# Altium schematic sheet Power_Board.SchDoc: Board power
size A3; Project: STM32MP15-DISCO; Date: Not used; ApprovedBy: Not used; CheckedBy: Not used; Author: Not used; CompanyName: STMicroelectronics; DrawnBy: Not used; Engineer: Not used; Organization: Not used; Address1: Not used; Address2: Not used; Address3: Not used; Address4: Not used; DocumentNumber: 5; Revision: Not used; SheetNumber: 5; SheetTotal: 17
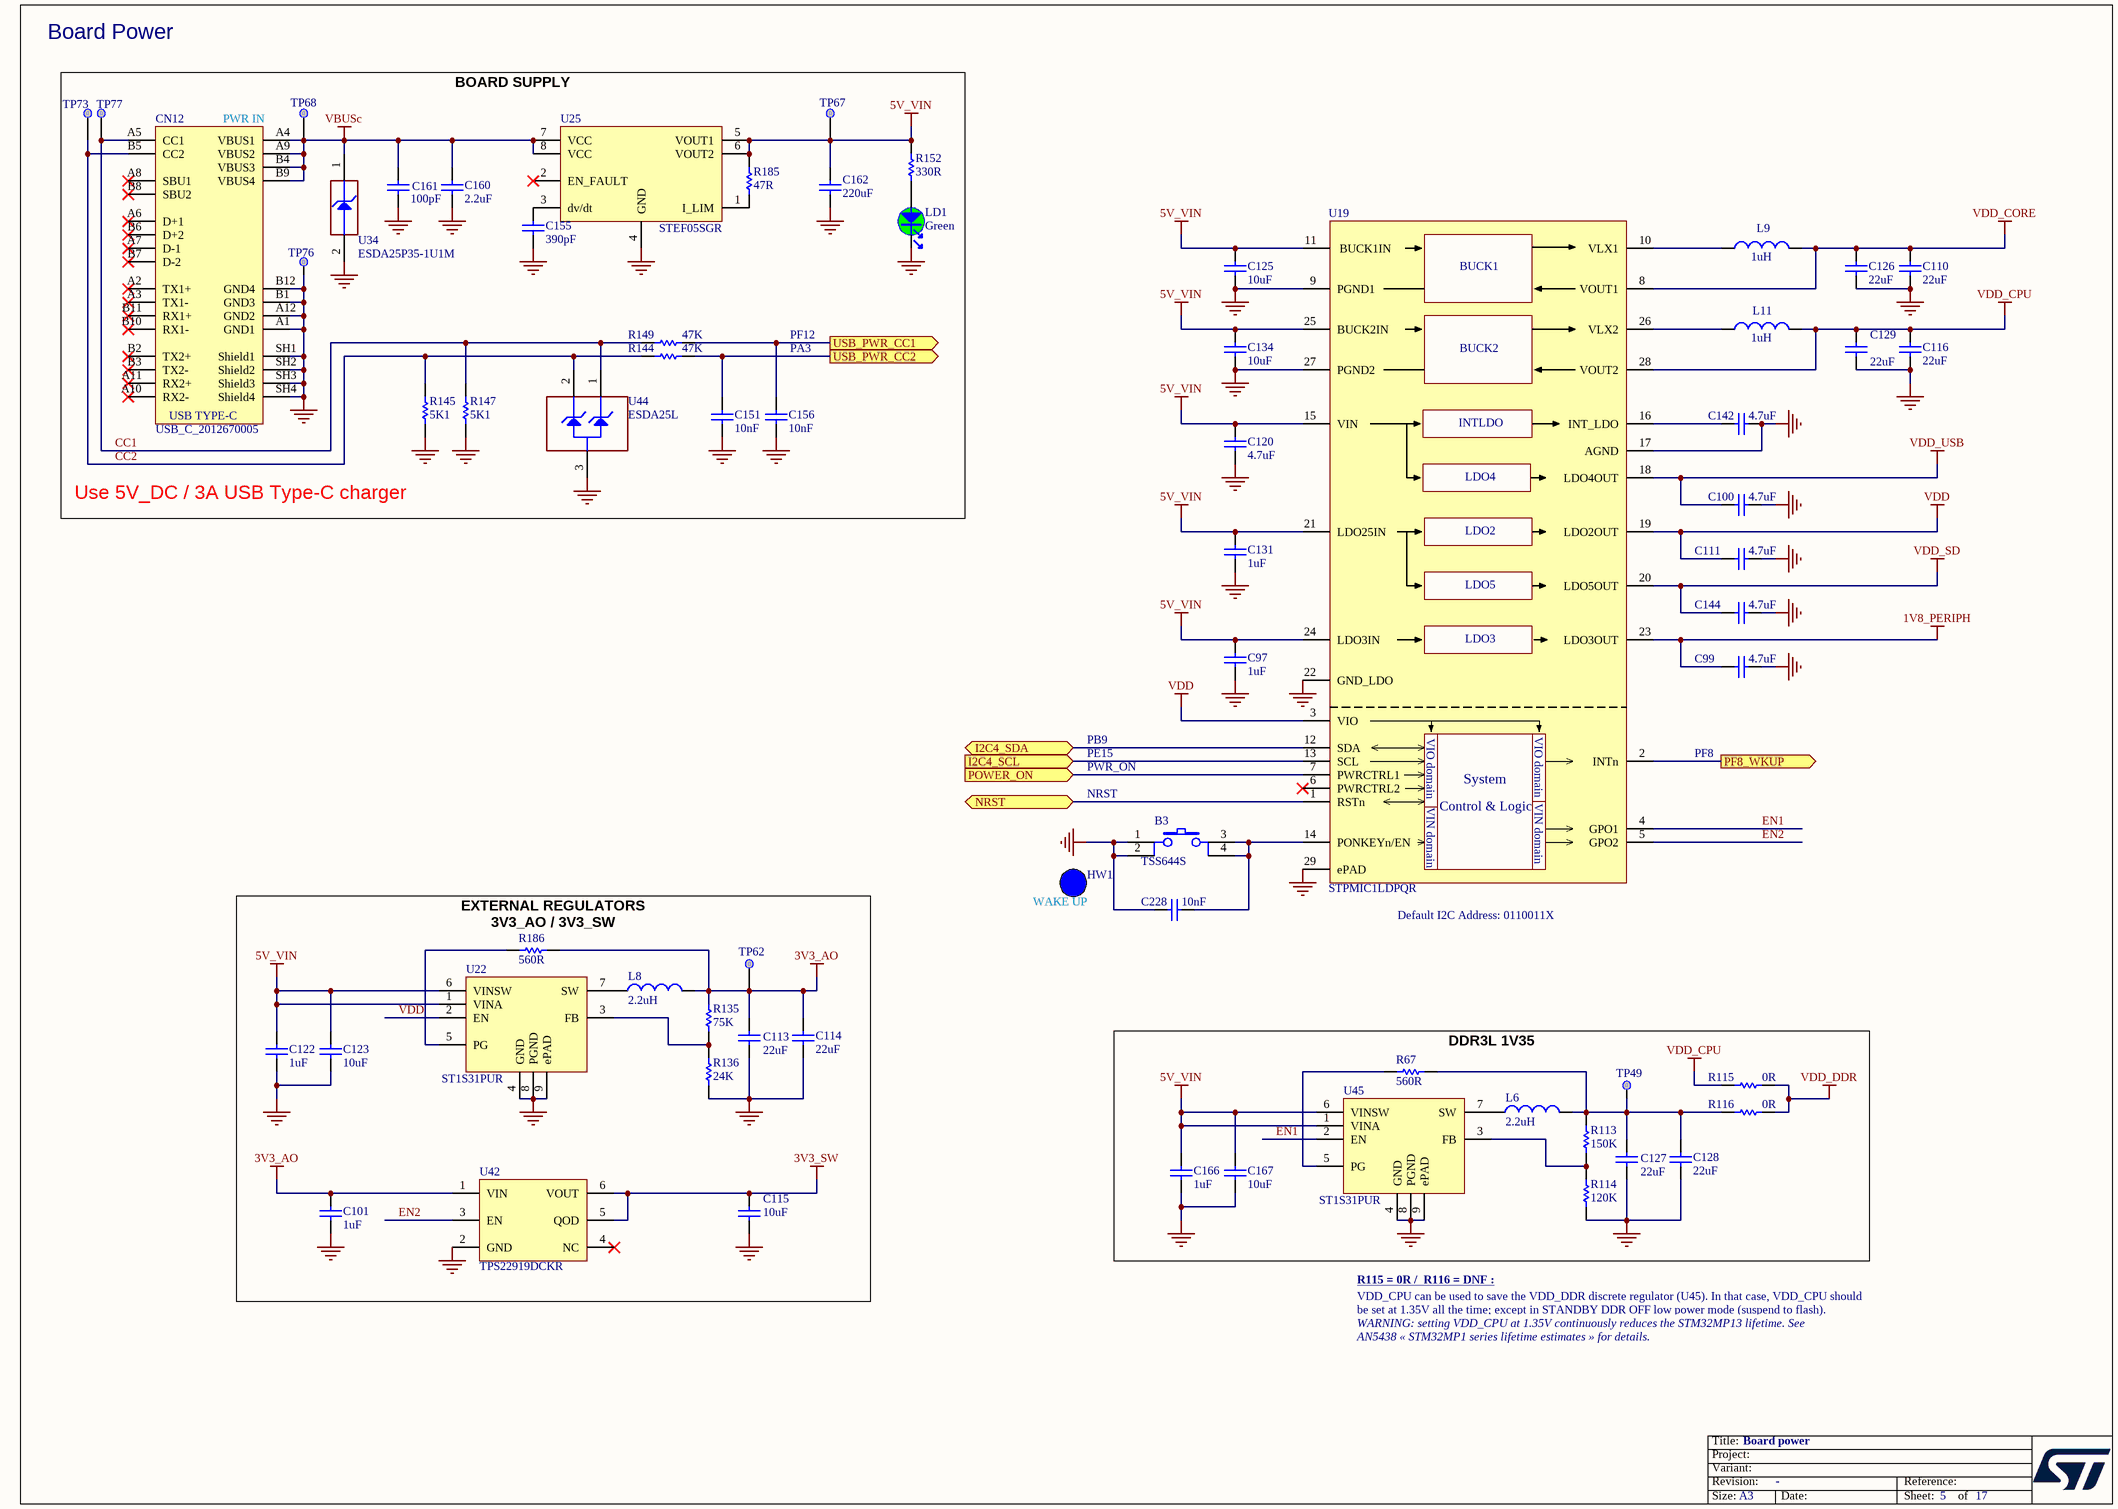
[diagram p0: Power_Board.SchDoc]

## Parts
B3  value TSS644S  [SWI_KNITTER_TSS644S]  (hidden comment: SW_PUSH_SMD)
C97  value 1uF  [C0402]  (hidden comment: Capacitor)
C99  value 4.7uF  [C0402]  (hidden comment: Capacitor)
C100  value 4.7uF  [C0402]  (hidden comment: Capacitor)
C101  value 1uF  [C0402]  (hidden comment: Capacitor)
C110  value 22uF  [C0603]  (hidden comment: Capacitor)
C111  value 4.7uF  [C0402]  (hidden comment: Capacitor)
C113  value 22uF  [C0603]  (hidden comment: Capacitor)
C114  value 22uF  [C0603]  (hidden comment: Capacitor)
C115  value 10uF  [C0603]  (hidden comment: Capacitor)
C116  value 22uF  [C0603]  (hidden comment: Capacitor)
C120  value 4.7uF  [C0402]  (hidden comment: Capacitor)
C122  value 1uF  [C0402]  (hidden comment: Capacitor)
C123  value 10uF  [C0603]  (hidden comment: Capacitor)
C125  value 10uF  [C0603]  (hidden comment: Capacitor)
C126  value 22uF  [C0603]  (hidden comment: Capacitor)
C127  value 22uF  [C0603]  (hidden comment: Capacitor)
C128  value 22uF  [C0603]  (hidden comment: Capacitor)
C129  value 22uF  [C0603]  (hidden comment: Capacitor)
C131  value 1uF  [C0402]  (hidden comment: Capacitor)
C134  value 10uF  [C0603]  (hidden comment: Capacitor)
C142  value 4.7uF  [C0402]  (hidden comment: Capacitor)
C144  value 4.7uF  [C0402]  (hidden comment: Capacitor)
C151  value 10nF  [C0402]  (hidden comment: Capacitor)
C155  value 390pF  [C0402]  (hidden comment: Capacitor)
C156  value 10nF  [C0402]  (hidden comment: Capacitor)
C160  value 2.2uF  [C0805]  (hidden comment: Capacitor)
C161  value 100pF  [C0402]  (hidden comment: Capacitor)
C162  value 220uF  [C1206_H1P6]  (hidden comment: Capacitor)
C166  value 1uF  [C0402]  (hidden comment: Capacitor)
C167  value 10uF  [C0603]  (hidden comment: Capacitor)
C228  value 10nF  [C0402]  (hidden comment: Capacitor)
CN12  value USB_C_2012670005  [CON_USB-TYPEC_MOLEX_2012670005]  (hidden comment: USB_TYPE_C_Receptacle)
HW1  AKTSC62B  (value not drawn)  (mechanical)
L6  value 2.2uH  [IND_2520_TOKO_DFE252012P]  (hidden comment: Inductor)
L8  value 2.2uH  [IND_2520_TOKO_DFE252012P]  (hidden comment: Inductor)
L9  value 1uH  [IND_2016_SAMSUNG_CIGT2016]  (hidden comment: Inductor)
L11  value 1uH  [IND_2016_SAMSUNG_CIGT2016]  (hidden comment: Inductor)
LD1  value Green  [LED_0603_GREEN]  (hidden comment: LED_green)
R67  value 560R  [R0402]  (hidden comment: Resistor)
R113  value 150K  [R0402]  (hidden comment: Resistor)
R114  value 120K  [R0402]  (hidden comment: Resistor)
R115  value 0R  [R0603]  (hidden comment: Resistor)
R116  value 0R  [R0603]  (hidden comment: Resistor)
R135  value 75K  [R0402]  (hidden comment: Resistor)
R136  value 24K  [R0402]  (hidden comment: Resistor)
R144  value 47K  [R0402]  (hidden comment: Resistor)
R145  value 5K1  [R0402]  (hidden comment: Resistor)
R147  value 5K1  [R0402]  (hidden comment: Resistor)
R149  value 47K  [R0402]  (hidden comment: Resistor)
R152  value 330R  [R0402]  (hidden comment: Resistor)
R185  value 47R  [R0402]  (hidden comment: Resistor)
R186  value 560R  [R0402]  (hidden comment: Resistor)
TP49  Test Point  [TP_SMD_1MM]  (value not drawn)  (no BOM)
TP62  Test Point  [TP_SMD_1MM]  (value not drawn)  (no BOM)
TP67  Test Point  [TP_SMD_1MM]  (value not drawn)  (no BOM)
TP68  Test Point  [TP_SMD_1MM]  (value not drawn)  (no BOM)
TP73  Test Point  [TP_SMD_1MM]  (value not drawn)  (no BOM)
TP76  Test Point  [TP_SMD_2MM]  (value not drawn)  (no BOM)
TP77  Test Point  [TP_SMD_1MM]  (value not drawn)  (no BOM)
U19  value STPMIC1LDPQR  [ICC_VFQFPN28-EPAD_4X4_P040]  (hidden comment: STPMIC1L)
U22  ST1S31PUR  [ICC_VFDFPN8-EPAD_3X3_P065]
U25  STEF05SGR  [ICC_TSOT23-8L]
U34  value ESDA25P35-1U1M  [ESD_QFN1610_2N_1K_2A]  (hidden comment: ESD-TRANSIL)
U42  value TPS22919DCKR  [ICC_SC70-6_DCK_R-PDSO-G6_2X1P25_P065]  (hidden comment: TPS22919)
U44  ESDA25L  [ESD_SOT23]
U45  ST1S31PUR  [ICC_VFDFPN8-EPAD_3X3_P065]

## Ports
I2C4_SCL (in), I2C4_SDA (bidir), NRST (bidir), PF8_WKUP (out), POWER_ON (in), USB_PWR_CC1 (out), USB_PWR_CC2 (out)

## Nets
1V8_PERIPH: C99.2 U19.23(LDO3OUT)
3V3_AO: C101.2 C113.2 C114.2 L8.2 R135.2 R186.2 TP62.1 U42.1(VIN)
3V3_SW: C115.2 U42.5(QOD) U42.6(VOUT)
5V_VIN: C97.2 C120.2 C122.2 C123.2 C125.2 C131.2 C134.2 C162.1 C166.2 C167.2 R152.2 R185.2 TP67.1 U19.11(BUCK1IN) U19.15(VIN) U19.21(LDO25IN) U19.24(LDO3IN) U19.25(BUCK2IN) U22.1(VINA) U22.6(VINSW) U25.5(VOUT1) U25.6(VOUT2) U45.1(VINA) U45.6(VINSW)
GND: B3.1 B3.2 C97.1 C99.1 C100.1 C101.1 C110.1 C111.1 C113.1 C114.1 C115.1 C116.1 C120.1 C122.1 C123.1 C125.1 C126.1 C127.1 C128.1 C129.1 C131.1 C134.1 C142.1 C144.1 C151.2 C155.1 C156.1 C160.1 C161.1 C162.2 C166.1 C167.1 C228.1 CN12.A1(GND1) CN12.A12(GND2) CN12.B1(GND3) CN12.B12(GND4) CN12.SH1(Shield1) CN12.SH2(Shield2) CN12.SH3(Shield3) CN12.SH4(Shield4) LD1.2 R114.1 R136.1 R145.1 R147.1 TP76.1 U19.9(PGND1) U19.17(AGND) U19.22(GND_LDO) U19.27(PGND2) U19.29(ePAD) U22.4(GND) U22.8(PGND) U22.9(ePAD) U25.4(GND) U34.2(GND) U42.2(GND) U44.3(GND) U45.4(GND) U45.8(PGND) U45.9(ePAD)
VBUSc: C160.2 C161.2 CN12.A4(VBUS1) CN12.A9(VBUS2) CN12.B4(VBUS3) CN12.B9(VBUS4) TP68.1 U25.7(VCC) U25.8(VCC) U34.1(IO1)
VDD: C111.2 U19.3(VIO) U19.19(LDO2OUT) U22.2(EN)
VDD_CORE: C110.2 C126.2 L9.2 U19.8(VOUT1)
VDD_CPU: C116.2 C129.2 L11.2 R115.1 U19.28(VOUT2)
VDD_DDR: R115.2 R116.2
VDD_SD: C144.2 U19.20(LDO5OUT)
VDD_USB: C100.2 U19.18(LDO4OUT)
CC1: CN12.A5(CC1) R147.2 R149.2 TP77.1 U44.1(IO1)
CC2: CN12.B5(CC2) R144.2 R145.2 TP73.1 U44.2(IO2)
EN1: U19.4(GPO1) U45.2(EN)
EN2: U19.5(GPO2) U42.3(EN)
I2C4_SCL: U19.13(SCL) ; port I2C4_SCL
I2C4_SDA: U19.12(SDA) ; port I2C4_SDA
NRST: U19.1(RSTn) ; port NRST
PF8_WKUP: U19.2(INTn) ; port PF8_WKUP
POWER_ON: U19.7(PWRCTRL1) ; port POWER_ON
USB_PWR_CC1: C156.2 R149.1 ; port USB_PWR_CC1
USB_PWR_CC2: C151.1 R144.1 ; port USB_PWR_CC2
NetB3_3: B3.3 B3.4 C228.2 U19.14(PONKEYn/EN)
NetC127_2: C127.2 C128.2 L6.2 R67.2 R113.2 R116.1 TP49.1
NetC142_2: C142.2 U19.16(INT_LDO)
NetC155_2: C155.2 U25.3(dv/dt)
NetL6_1: L6.1 U45.7(SW)
NetL8_1: L8.1 U22.7(SW)
NetL9_1: L9.1 U19.10(VLX1)
NetL11_1: L11.1 U19.26(VLX2)
NetLD1_1: LD1.1 R152.1
NetR67_1: R67.1 U45.5(PG)
NetR113_1: R113.1 R114.2 U45.3(FB)
NetR135_1: R135.1 R136.2 U22.3(FB)
NetR185_1: R185.1 U25.1(I_LIM)
NetR186_1: R186.1 U22.5(PG)

Not connected (* = marked no-connect by the designer): CN12 A2(TX1+)* A3(TX1-)* A6(D+1)* A7(D-1)* A8(SBU1)* A10(RX2-)* A11(RX2+)* B2(TX2+)* B3(TX2-)* B6(D+2)* B7(D-2)* B8(SBU2)* B10(RX1-)* B11(RX1+)*; U19 6(PWRCTRL2)*; U25 2(EN_FAULT)*; U42 4(NC)*

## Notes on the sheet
- Board Power
- (near CN12) PWR IN
- PA3
- PF12
- BOARD SUPPLY
- Use 5V_DC / 3A USB Type-C charger
- PB9
- PE15
- PWR_ON
- PF8
- NRST
- (near HW1) WAKE UP
- (near U19) Default I2C Address: 0110011X
- DDR3L 1V35
- EXTERNAL REGULATORS
  3V3_AO / 3V3_SW
- VDD_CPU can be used to save the VDD_DDR discrete regulator (U45). In that case, VDD_CPU should be set at 1.35V all the time; except in STANDBY DDR OFF low power mode (suspend to flash).
- R115 = 0R /  R116 = DNF :
- WARNING: setting VDD_CPU at 1.35V continuously reduces the STM32MP13 lifetime. See AN5438 « STM32MP1 series lifetime estimates » for details.

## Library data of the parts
B3 = MCD-02417: Push Button, NO, 0.05A, 12V, Salmon; Part_Type: Misc; Manufacturer: KNITTER-SWITCH; Part_Preference: Recommended; Manufacturer_HQ_COO: Unknown; Partial_Alternate_Internal_Part_Number: MCD-03589; Component_Country_Of_Origin: China; ShowFields: YES; ID: 4523
C97 C122 C131 C166 = MCD-00095: Capacitor, MLCC, 1uF, 25V, X5R, 10%, 0402, T=0.5mm; Part_Preference: Recommended; Manufacturer: MURATA; Manufacturer_Part_Number: GRM155R61E105KA12; Partial_Alternate_Internal_Part_Number: MCD-04188; Order_Code_RS: 2218855; Component_Country_Of_Origin: Japan°°; ShowFields: YES; ID: 2772
C99 C100 C111 C120 C142 C144 = MCD-01356: Capacitor, MLCC, 4.7uF, 6V3, X5R, 20%, 0402, T=0.5mm; Manufacturer_Part_Number: GRM155R60J475ME47; Manufacturer: MURATA; Part_Preference: Recommended; Partial_Alternate_Internal_Part_Number: MCD-04455; Order_Code_RS: 814-5230; Component_Country_Of_Origin: Japan°°; ShowFields: YES; ID: 3456
C101 = MCD-00095: Capacitor, MLCC, 1uF, 25V, X5R, 10%, 0402, T=0.5mm; Manufacturer_Part_Number: GRM155R61E105KA12; Manufacturer: MURATA; Part_Preference: Recommended; Partial_Alternate_Internal_Part_Number: MCD-04188; Order_Code_RS: 2218855; Component_Country_Of_Origin: Japan°°; ID: 2772; ShowFields: YES
C110 C116 C126 C129 = MCD-00100: Capacitor, MLCC, 22uF, 6V3, X5R, +/-20%, 0603, T=0.8mm; Manufacturer_Part_Number: GRM188R60J226MEA0; Manufacturer: MURATA; Part_Preference: Recommended; Partial_Alternate_Internal_Part_Number: MCD-04184; Component_Country_Of_Origin: Japan°°; ShowFields: YES; ID: 2766
C113 C114 C127 C128 = MCD-00100: Capacitor, MLCC, 22uF, 6V3, X5R, +/-20%, 0603, T=0.8mm; Part_Preference: Recommended; Manufacturer: MURATA; Manufacturer_Part_Number: GRM188R60J226MEA0; Partial_Alternate_Internal_Part_Number: MCD-04184; Component_Country_Of_Origin: Japan°°; ShowFields: YES; ID: 2766
C115 = MCD-00099: Capacitor, MLCC, 10uF, 10V, X5R, +/-10%, 0603, T=0.8mm; Manufacturer_Part_Number: GRM188R61A106KE69; Manufacturer: MURATA; Part_Preference: Recommended; Partial_Alternate_Internal_Part_Number: MCD-03152; Order_Code_RS: 2494233; Component_Country_Of_Origin: Japan°°; ID: 2770; ShowFields: YES
C123 C167 = MCD-00099: Capacitor, MLCC, 10uF, 10V, X5R, +/-10%, 0603, T=0.8mm; Part_Preference: Recommended; Manufacturer: MURATA; Manufacturer_Part_Number: GRM188R61A106KE69; Partial_Alternate_Internal_Part_Number: MCD-03152; Order_Code_RS: 2494233; Component_Country_Of_Origin: Japan°°; ShowFields: YES; ID: 2770
C125 C134 = MCD-00099: Capacitor, MLCC, 10uF, 10V, X5R, +/-10%, 0603, T=0.8mm; Manufacturer_Part_Number: GRM188R61A106KE69; Manufacturer: MURATA; Part_Preference: Recommended; Partial_Alternate_Internal_Part_Number: MCD-03152; Order_Code_RS: 2494233; Component_Country_Of_Origin: Japan°°; ShowFields: YES; ID: 2770
C151 C156 = MCD-02198: Capacitor, MLCC, 10nF, 50V, X7R, +/-10%, 0402, T=0.5mm; Part_Preference: Recommended; Manufacturer: YAGEO; Manufacturer_Part_Number: CC0402KRX7R9BB103; Order_Code_RS: 6169644; Component_Country_Of_Origin: China; ShowFields: YES; ID: 4298
C155 = MCD-01481: Capacitor, MLCC, 390pF, 50V, C0G/NP0, +/-5%, 0402, T=0.5mm; Part_Preference: Recommended; Manufacturer: YAGEO; Manufacturer_Part_Number: CC0402JRNPO9BN391; Component_Country_Of_Origin: China; ShowFields: YES; ID: 3581
C160 = MCD-02372: Capacitor, MLCC, 2.2uF, 25V, X7R, +/-10%, 0805, T=1,25mm; Part_Preference: Recommended; Manufacturer: MURATA; Manufacturer_Part_Number: GRM21BR71E225KE11; Partial_Alternate_Internal_Part_Number: MCD-04185; Component_Country_Of_Origin: Japan°; ShowFields: YES; ID: 4478
C161 = MCD-00205: Capacitor, MLCC, 100pF, 50V, C0G/NP0, +/-5%, 0402, T=0.5mm; Manufacturer_Part_Number: CC0402JRNPO9BN101; Manufacturer: YAGEO; Part_Preference: Recommended; Component_Country_Of_Origin: China; ShowFields: YES; ID: 2658
C162 = MCD-00104: Capacitor, MLCC, 220uF, 6V3, X5R, +/-20%, 1206, T=1.6mm; Manufacturer_Part_Number: GRM31CR60J227ME11; Manufacturer: MURATA; Part_Preference: Recommended; Order_Code_RS: 170-6396; Component_Country_Of_Origin: Japan°°; ShowFields: YES; ID: 2764
C228 = MCD-02198: Capacitor, MLCC, 10nF, 50V, X7R, +/-10%, 0402, T=0.5mm; Manufacturer_Part_Number: CC0402KRX7R9BB103; Manufacturer: YAGEO; Part_Preference: Recommended; Order_Code_RS: 6169644; Component_Country_Of_Origin: China; ShowFields: YES; ID: 4298
CN12 = MCD-02421: USB_TypeC, 24 pins, RA, SMD, T=3.71mm (USB Certified 3.1); Part_Type: Connector; Manufacturer_Part_Number: 2012670005; Manufacturer: MOLEX; Part_Preference: Recommended; Order_Code_RS: 176-8434; Component_Country_Of_Origin: Unknown; ShowFields: YES; ID: 4527
HW1 = MCD-02136: Round cap, Blue, 6x6mm; Part_Type: Mechanical; Part_Preference: Recommended; Manufacturer: APEM; Partial_Alternate_Internal_Part_Number: MCD-02419; Order_Code_RS: 378-6779; Component_Country_Of_Origin: Unknown; ShowFields: YES; ID: 4236
L6 L8 = MCD-00161: Inductor, 2.2uH, +/-20%, 2,2A, 84mR, 1008, T=1.2mm; Part_Preference: Recommended; Manufacturer: TOKO; Manufacturer_Part_Number: DFE252012P-2R2M=P2; Order_Code_RS: 167-0606; Component_Country_Of_Origin: Japan°°; ShowFields: YES; ID: 2711
L9 L11 = MCD-04058: Inductor, 1uH, +/-20%, 3.6A, 57mR, 0806, T=1mm; Part_Preference: Recommended; Manufacturer: SAMSUNG ELECTRO-MECHANICS; Manufacturer_Part_Number: CIGT201610LH1R0MNE; ShowFields: YES; ID: 6174; Component_Country_Of_Origin: Unknown
LD1 = MCD-00050: LED, Green, 2V, 20mA, 0603; Part_Type: Display; Manufacturer_Part_Number: 19-213SYGC/S530-E2/TR8; Manufacturer: EVERLIGHT; Part_Preference: Forbidden; Partial_Alternate_Internal_Part_Number: MCD-02900; Component_Country_Of_Origin: China; ShowFields: YES; ID: 2542
R67 R186 = MCD-00489: Resistor, 560R, 0402, +/-1%, 1/16W; Part_Preference: Recommended; Manufacturer: YAGEO; Manufacturer_Part_Number: RC0402FR-07560RL; Component_Country_Of_Origin: China; ShowFields: YES; ID: 2789
R113 = MCD-00165: Resistor, 150K, 0402, +/-1%, 1/16W; BMS_Part_Number: 9131032; Part_Preference: Recommended; Manufacturer: YAGEO; Manufacturer_Part_Number: RC0402FR-07150KL; Component_Country_Of_Origin: China; ShowFields: YES; ID: 2702
R114 = MCD-00166: Resistor, 120K, 0402, +/-1%, 1/16W; Part_Preference: Recommended; Manufacturer: YAGEO; Manufacturer_Part_Number: RC0402FR-07120KL; Component_Country_Of_Origin: China; ShowFields: YES; ID: 2703
R115 R116 = MCD-00181: Resistor, 0R, 0603, +/- 0.5mR, 1/4W; Part_Preference: Recommended; Manufacturer: ROHM SEMICONDUCTOR; Manufacturer_Part_Number: PMR03EZPJ000; Component_Country_Of_Origin: Philippines, Thailand°°; ShowFields: YES; ID: 2691
R135 = MCD-00521: Resistor, 75K, 0402, +/-1%, 1/16W; Part_Preference: Recommended; Manufacturer: YAGEO; Manufacturer_Part_Number: RC0402FR-0775KL; Component_Country_Of_Origin: China; ShowFields: YES; ID: 3220
R136 = MCD-00435: Resistor, 24K, 0402, +/-1%, 1/16W; Part_Preference: Recommended; Manufacturer: YAGEO; Manufacturer_Part_Number: RC0402FR-0724KL; Component_Country_Of_Origin: China; ShowFields: YES; ID: 2845
R144 R149 = MCD-00063: Resistor, 47K, 0402, +/-1%, 1/16W; Manufacturer_Part_Number: RC0402FR-0747KL; Manufacturer: YAGEO; Part_Preference: Recommended; Order_Code_RS: 9239430; Component_Country_Of_Origin: China; ShowFields: YES; ID: 2528
R145 R147 = MCD-00333: Resistor, 5K1, 0402, +/-1%, 1/16W; Part_Preference: Recommended; Manufacturer: YAGEO; Manufacturer_Part_Number: RC0402FR-075K1L; Component_Country_Of_Origin: China; ShowFields: YES; ID: 2944
R152 = MCD-00062: Resistor, 330R, 0402, +/-1%, 1/16W; Manufacturer_Part_Number: RC0402FR-07330RL; Manufacturer: YAGEO; Part_Preference: Recommended; Order_Code_RS: 9239170; Component_Country_Of_Origin: China; ShowFields: YES; ID: 2529
R185 = MCD-00481: Resistor, 47R, 0402, +/-1%, 1/16W; Part_Preference: Recommended; Manufacturer: YAGEO; Manufacturer_Part_Number: RC0402FR-0747RL; Component_Country_Of_Origin: China; ShowFields: YES; ID: 2796
TP49 TP62 TP67 TP68 TP73 TP77 = MCD-00074: Test Point, SMD, 1mm; Part_Type: Misc; Part_Preference: Recommended; ShowFields: YES; ID: 2518; Component_Country_Of_Origin: Unknown
TP76 = MCD-00177: Test Point, SMD, 2mm; Part_Type: Misc; Part_Preference: Recommended; ShowFields: YES; ID: 2690; Component_Country_Of_Origin: Unknown
U19 = MCD-04949: Power Management IC for STM32MP13xD/F series (overdrive) with 2 step-down SMPS, 4 LDOs, 2 GPOs, WFQFN 28L (4.0 x 4.0 x 1.0 mm); Part_Preference: Recommended; Manufacturer: STMICROELECTRONICS; ShowFields: YES; ID: 7065
U22 U45 = MCD-02243: Regulator, 3A, DC step-down switching; Part_Type: IC; Part_Preference: Recommended; Manufacturer: STMICROELECTRONICS; Manufacturer_HQ_COO: EU; Order_Code_RS: 168-7852; Component_Country_Of_Origin: Malaysia; ShowFields: YES; ID: 4343
U25 = MCD-03955: IC, Electronic fuse for 5V line, Vclamp 5V7, Vin max 25V; Part_Preference: Recommended; Manufacturer: STMICROELECTRONICS; Component_Country_Of_Origin: Malaysia; ShowFields: YES; ID: 6071
U34 = MCD-01207: Diode, ESD TVS, 22V, 200nA, 25V8, QFN1610; BMS_Part_Number: 9179045; Part_Preference: Recommended; Manufacturer: STMICROELECTRONICS; Manufacturer_HQ_COO: EU; Component_Country_Of_Origin: China; ShowFields: YES; ID: 3289; Order_Code_RS: 163-9774
U42 = MCD-02311: IC, 5V5, 1.5A, 90mR Self-Protected load switch with controlled rise time; Part_Preference: Recommended; Manufacturer: TEXAS INSTRUMENTS; Component_Country_Of_Origin: Thailand; ID: 4417; ShowFields: YES
U44 = MCD-01125: Diode, ESD Transil, 24V, 1uA, 30V, SOT23-3; Part_Preference: Recommended; Manufacturer: STMICROELECTRONICS; Manufacturer_HQ_COO: EU; Order_Code_RS: 795-8757; Component_Country_Of_Origin: Malaysia; ShowFields: YES; ID: 3364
